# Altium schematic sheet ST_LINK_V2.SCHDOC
size A4; DocumentNumber: 2; Revision: A.1(PCB.SCH); SheetNumber: 2; SheetTotal: 3
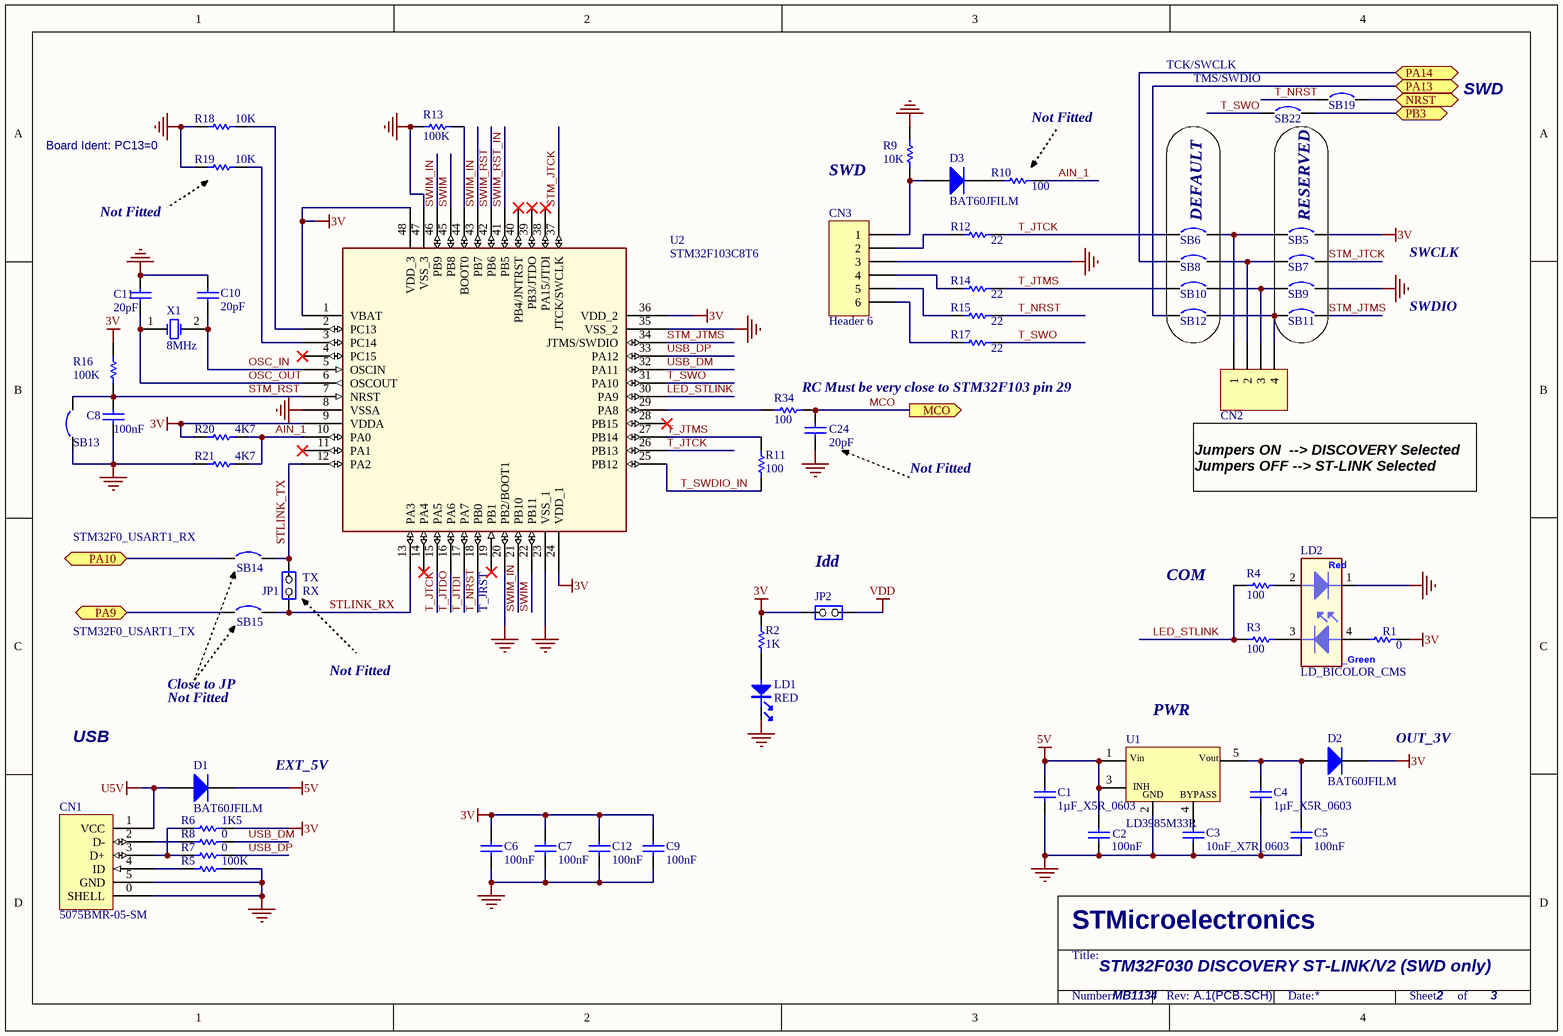
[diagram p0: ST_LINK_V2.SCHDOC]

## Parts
C1  1µF_X5R_0603  [0603C]
C2  100nF  [0603C]
C3  10nF_X7R_0603  [0603C]
C4  1µF_X5R_0603  [0603C]
C5  100nF  [0603C]
C6  100nF  [0402C]
C7  100nF  [0402C]
C8  100nF  [0402C]
C9  100nF  [0402C]
C10  20pF  [0402C]
C11  20pF  [0402C]
C12  100nF  [0402C]
C24  20pF  [0402C]
CN1  5075BMR-05-SM  [USB-MINI-B-SMD]
CN2  Header 4  [Header 4]  (value not drawn)
CN3  Header 6  [HDR1X6]
D1  BAT60JFILM  [SOD323/A]
D2  BAT60JFILM  [SOD323/A]
D3  BAT60JFILM  [SOD323/A]
JP1  (no value)  [SIP2/2.54]
JP2  (no value)  [SIP2/2.54]
LD1  RED  [0603D]
LD2  LD_BICOLOR_CMS  [HSMF-A201]
R1  0  [0402R]
R2  1K  [0402R]
R3  100  [0402R]
R4  100  [0402R]
R5  100K  [0402R]
R6  1K5  [0402R]
R7  0  [0603R-GS]
R8  0  [0603R-GS]
R9  10K  [0402R]
R10  100  [0402R]
R11  100  [0402R]
R12  22  [0402R]
R13  100K  [0402R]
R14  22  [0402R]
R15  22  [0402R]
R16  100K  [0402R]
R17  22  [0402R]
R18  10K  [0402R]
R19  10K  [0402R]
R20  4K7  [0402R]
R21  4K7  [0402R]
R34  100  [0402R]
SB5  Circuit Breaker  [JP2_SMD]  (value not drawn)
SB6  Circuit Breaker  [JP2_SMD]  (value not drawn)
SB7  Circuit Breaker  [JP2_SMD]  (value not drawn)
SB8  Circuit Breaker  [JP2_SMD]  (value not drawn)
SB9  Circuit Breaker  [JP2_SMD]  (value not drawn)
SB10  Circuit Breaker  [JP2_SMD]  (value not drawn)
SB11  Circuit Breaker  [JP2_SMD]  (value not drawn)
SB12  Circuit Breaker  [JP2_SMD]  (value not drawn)
SB13  Circuit Breaker  [JP2_SMD]  (value not drawn)
SB14  Circuit Breaker  [JP2_SMD]  (value not drawn)
SB15  Circuit Breaker  [JP2_SMD]  (value not drawn)
SB19  Circuit Breaker  [JP2_SMD]  (value not drawn)
SB22  Circuit Breaker  [JP2_SMD]  (value not drawn)
U1  LD3985M33R  [SOT-23-5L]
U2  STM32F103C8T6  [QFP48 7X7]
X1  8MHz  [XTAL1]

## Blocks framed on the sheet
DEFAULT: SB6 SB8 SB10 SB12
RESERVED: SB5 SB7 SB9 SB11

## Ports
MCO (out), NRST, PA9, PA10, PA13, PA14, PB3

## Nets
3V: C6.2 C7.2 C9.2 C12.1 D2.2(K) JP2.1(COMMON) R1.2 R2.2 R6.2 R16.2 R20.1 SB5.2 U2.1(VBAT) U2.9(VDDA) U2.24(VDD_1) U2.36(VDD_2) U2.48(VDD_3)
5V: C1.2 C2.2 D1.2(K) U1.1(Vin) U1.3(CE)
GND: C1.1 C2.1 C3.1 C4.2 C5.1 C6.1 C7.1 C8.1 C9.1 C10.1 C11.1 C12.2 C24.2 CN1.0(SHELL) CN1.5(GND) CN3.3 LD1.2 LD2.1 R5.2 R9.2 R13.1 R18.1 R19.1 R21.1 SB9.2 SB13.1 U1.2(GND) U2.8(VSSA) U2.20(PB2/BOOT1) U2.23(VSS_1) U2.35(VSS_2) U2.47(VSS_3)
U5V: CN1.1(VCC) D1.1(A)
VDD: JP2.2(NO)
AIN_1: R10.2 R20.2 R21.2 U2.10(PA0)
LED_STLINK: R3.1 R4.1 U2.30(PA9)
MCO: C24.1 R34.2 ; port MCO
NRST: SB19.2 ; port NRST
OSC_IN: C10.2 U2.5(OSCIN) X1.2(OSC2)
OSC_OUT: C11.2 U2.6(OSCOUT) X1.1(OSC1)
PA9: SB15.1 ; port PA9
PA10: SB14.1 ; port PA10
PA13: SB12.1 ; port PA13
PA14: SB8.1 ; port PA14
PB3: SB22.2 ; port PB3
STLINK_RX: JP1.1(COMMON) SB15.2 U2.13(PA3)
STLINK_TX: JP1.2(NO) SB14.2 U2.12(PA2)
STM_JTCK: SB7.2 U2.37(JTCK/SWCLK)
STM_JTMS: SB11.2 U2.34(JTMS/SWDIO)
STM_RST: C8.2 R16.1 SB13.2 U2.7(NRST)
SWIM: U2.22(PB11) U2.45(PB8)
SWIM_IN: U2.21(PB10) U2.43(PB7) U2.46(PB9)
SWIM_RST: U2.42(PB6)
SWIM_RST_IN: U2.41(PB5)
T_JTCK: R12.2 SB6.1 U2.15(PA5) U2.26(PB13)
T_JTDI: U2.17(PA7)
T_JTDO: U2.16(PA6)
T_JTMS: R11.2 R14.2 SB10.1 U2.27(PB14)
T_NRST: R15.2 SB19.1 U2.18(PB0)
T_SWDIO_IN: R11.1 U2.25(PB12)
T_SWO: R17.2 SB22.1 U2.31(PA10)
USB_DM: R8.2 U2.32(PA11)
USB_DP: R7.2 U2.33(PA12)
NetC3_2: C3.2 U1.4(BYPASS)
NetC4_1: C4.1 C5.2 D2.1(A) U1.5(Vout)
NetCN1_2: CN1.2(D-) R8.1
NetCN1_3: CN1.3(D+) R6.1 R7.1
NetCN1_4: CN1.4(ID) R5.1
NetCN2_1: CN2.1 SB5.1 SB6.2
NetCN2_2: CN2.2 SB7.1 SB8.2
NetCN2_3: CN2.3 SB9.1 SB10.2
NetCN2_4: CN2.4 SB11.1 SB12.2
NetCN3_1: CN3.1 D3.1(A) R9.1
NetCN3_2: CN3.2 R12.1
NetCN3_4: CN3.4 R14.1
NetCN3_5: CN3.5 R15.1
NetCN3_6: CN3.6 R17.1
NetD3_2: D3.2(K) R10.1
NetLD1_1: LD1.1 R2.1
NetLD2_2: LD2.2 R4.2
NetLD2_3: LD2.3 R3.2
NetLD2_4: LD2.4 R1.1
NetR13_2: R13.2 U2.44(BOOT0)
NetR18_2: R18.2 U2.2(PC13)
NetR19_2: R19.2 U2.3(PC14)
NetR34_1: R34.1 U2.29(PA8)

Not connected (* = marked no-connect by the designer): U2 4(PC15)* 11(PA1)* 14(PA4)* 19(PB1)* 28(PB15)* 38(PA15/JTDI)* 39(PB3/JTDO)* 40(PB4/JNTRST)*

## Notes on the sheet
- TCK/SWCLK
- (near SB22) TMS/SWDIO
- SWD
- Board Ident: PC13=0
- Not Fitted
- SWCLK
- SWDIO
- (near R34) RC Must be very close to STM32F103 pin 29
- Jumpers ON  --> DISCOVERY Selected
  Jumpers OFF --> ST-LINK Selected
- STM32F0_USART1_RX
- (near JP1) TX
- (near JP2) Idd
- COM
- STM32F0_USART1_TX
- (near JP1) RX
- (near U2) T_JRST
- Close to JP
- (near U1) PWR
- USB
- EXT_5V
- OUT_3V
- STM32F030 DISCOVERY ST-LINK/V2 (SWD only)
- MB1134

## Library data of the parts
C1 C4 = CAP SMD 0603  X5R 1µF 25V 10%: 0603  X5R 1µF; Rated voltage: 25V; Tolerance: 10%
C2 C5-C12 = Cap: Capacitor
C3 = CAP SMD 0603  X7R 10000PF 50V 10%: 0603  X7R 10NF; Order code RS: 2040779; Rated voltage: 50V; Tolerance: 10%
C24 = Cap: Capacitor; Fitted: NO
CN1 = USB-MINI-typeB connector
CN2 = Header 4: Header, 4-Pin; Description: Header 4x1 with 2 Jumpers
CN3 = Header 6: Header, 6-Pin
D1-D3 = BAT60JFILM: Manuf_1: STM; Code - JEDEC: DO-214-AB; Provided: ST
JP1 = JP2: Fitted: NO
JP2 = JP2: Description: Header 2x1 with Jumper
LD1 = PHOTO
LD2 = LD_BICOLOR_CMS: Bicolor Led; Manuf_Part_1: HSMF-A201-A00J1; Manuf_1: Avago Technologies; Ref St: xxxxxx; cap_dec: ----
R1-R6 R9 R11-R18 R20 R21 R34 = res1: Resistor
R7 R8 = res1: Resistor; Value: 10
R10 R19 = res1: Resistor; Fitted: NO
SB5 SB7 SB9 SB11 SB19 SB22 = Circuit Breaker: Solder: YES
SB6 SB8 SB10 SB12-SB15 = Circuit Breaker: Solder: NO
U1 = LD3985M33R: Ultra low drop-low noise BiCMOS voltage, regulators low ESR capacitors compatible; Manuf_1: STM; Provided: ST; Ref St: 9176161
U2 = STM32F103C8T6: Medium-density performance line ARM-based 32-bit MCU with 64KB Flash, USB, CAN, 7 timers, 2 ADCs; Manuf_1: STM; Ref St: 9175981; Provided: ST
X1 = XTAL: Crystal Oscillator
